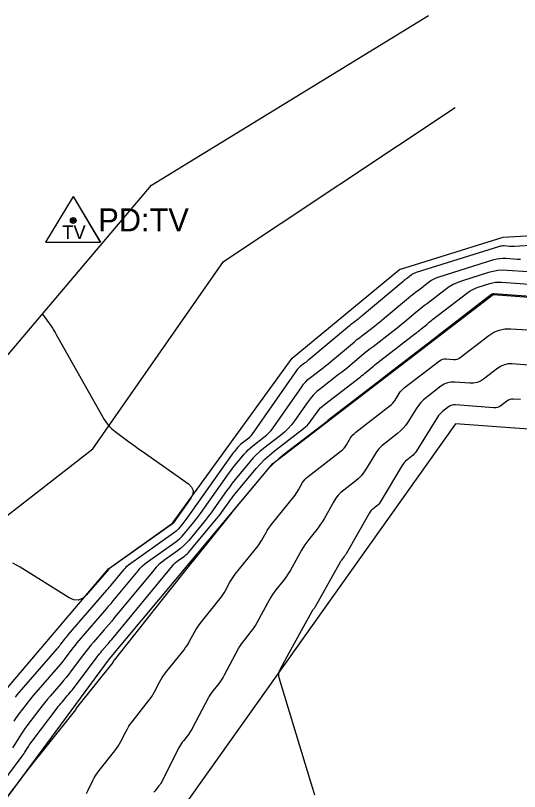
# Model space of a CAD drawing. Extents: x 1574966 to 1597594, y 720505 to 737840.
# Drawn here: x 1577580.8 to 1577690.4, y 724330.5 to 724499.2 of the extents above; entities that cross this region are included whole.
import ezdxf

# ---------------------------------------------------------------- set-up
doc = ezdxf.new("R2010")
doc.units = 0
for name, color, linetype in [('Default', 7, 'Continuous'), ('R_Contours', 7, 'Continuous'), ('S_BREAKLINE', 7, 'Continuous'), ('S_SECONDARY_CTL', 7, 'Continuous'), ('S_SECONDARY_CTL_ANNOT', 7, 'Continuous'), ('S_STREAM', 7, 'Continuous')]:
    doc.layers.add(name, color=color, linetype=linetype)

msp = doc.modelspace()

# ---------------------------------------------------------------- linework, layer by layer
at = {"layer": 'Default'}
for points in [[(1577593.33, 724454.59), (1577593.33, 724454.64), (1577593.33, 724454.59), (1577593.28, 724454.59), (1577593.33, 724454.59), (1577593.33, 724454.54), (1577593.33, 724454.59), (1577593.38, 724454.59)], [(1577593.33, 724454.59), (1577593.33, 724454.64), (1577593.33, 724454.59), (1577593.28, 724454.59), (1577593.33, 724454.59), (1577593.33, 724454.54), (1577593.33, 724454.59), (1577593.38, 724454.59)], [(1577593.33, 724454.59), (1577593.33, 724454.64), (1577593.33, 724454.59), (1577593.28, 724454.59), (1577593.33, 724454.59), (1577593.33, 724454.54), (1577593.33, 724454.59), (1577593.38, 724454.59)], [(1577593.33, 724454.58), (1577593.33, 724454.63), (1577593.33, 724454.58), (1577593.28, 724454.58), (1577593.33, 724454.58), (1577593.33, 724454.53), (1577593.33, 724454.58), (1577593.38, 724454.58)], [(1577593.33, 724454.58), (1577593.33, 724454.63), (1577593.33, 724454.58), (1577593.28, 724454.58), (1577593.33, 724454.58), (1577593.33, 724454.53), (1577593.33, 724454.58), (1577593.38, 724454.58)], [(1577593.33, 724454.58), (1577593.33, 724454.63), (1577593.33, 724454.58), (1577593.28, 724454.58), (1577593.33, 724454.58), (1577593.33, 724454.53), (1577593.33, 724454.58), (1577593.38, 724454.58)], [(1577593.36, 724454.57), (1577593.36, 724454.62), (1577593.36, 724454.57), (1577593.31, 724454.57), (1577593.36, 724454.57), (1577593.36, 724454.52), (1577593.36, 724454.57), (1577593.41, 724454.57)], [(1577593.36, 724454.57), (1577593.36, 724454.62), (1577593.36, 724454.57), (1577593.31, 724454.57), (1577593.36, 724454.57), (1577593.36, 724454.52), (1577593.36, 724454.57), (1577593.41, 724454.57)], [(1577593.36, 724454.57), (1577593.36, 724454.62), (1577593.36, 724454.57), (1577593.31, 724454.57), (1577593.36, 724454.57), (1577593.36, 724454.52), (1577593.36, 724454.57), (1577593.41, 724454.57)], [(1577593.36, 724454.56), (1577593.36, 724454.61), (1577593.36, 724454.56), (1577593.31, 724454.56), (1577593.36, 724454.56), (1577593.36, 724454.51), (1577593.36, 724454.56), (1577593.41, 724454.56)], [(1577593.36, 724454.56), (1577593.36, 724454.61), (1577593.36, 724454.56), (1577593.31, 724454.56), (1577593.36, 724454.56), (1577593.36, 724454.51), (1577593.36, 724454.56), (1577593.41, 724454.56)], [(1577593.36, 724454.56), (1577593.36, 724454.61), (1577593.36, 724454.56), (1577593.31, 724454.56), (1577593.36, 724454.56), (1577593.36, 724454.51), (1577593.36, 724454.56), (1577593.41, 724454.56)]]:
    msp.add_lwpolyline(points, dxfattribs=at)
at = {"layer": 'R_Contours'}
for points in [[(1577699.92, 724449.62), (1577689.3, 724449), (1577689.03, 724448.99), (1577688.76, 724448.99), (1577688.48, 724448.99), (1577688.21, 724449.01), (1577687.11, 724449.09), (1577686.84, 724449.09), (1577686.57, 724449.08), (1577686.31, 724449.03), (1577686.04, 724448.96), (1577667.93, 724443.31), (1577667.66, 724443.21), (1577667.41, 724443.09), (1577667.16, 724442.95), (1577666.93, 724442.79), (1577666.03, 724442.09), (1577665.8, 724441.92), (1577665.58, 724441.74), (1577665.36, 724441.56), (1577665.14, 724441.38), (1577656.22, 724433.93), (1577656, 724433.74), (1577655.77, 724433.56), (1577655.54, 724433.38), (1577655.31, 724433.2), (1577654.38, 724432.48), (1577654.14, 724432.3), (1577653.91, 724432.12), (1577653.68, 724431.93), (1577653.46, 724431.75), (1577644.63, 724424.37), (1577644.39, 724424.17), (1577644.16, 724423.98), (1577643.92, 724423.8), (1577643.68, 724423.61), (1577642.72, 724422.87), (1577642.49, 724422.68), (1577642.27, 724422.47), (1577642.07, 724422.25), (1577641.89, 724422.01), (1577632.2, 724408.12), (1577631.99, 724407.84), (1577631.76, 724407.58), (1577631.52, 724407.34), (1577631.25, 724407.12), (1577630.1, 724406.24), (1577629.85, 724406.03), (1577629.61, 724405.82), (1577629.39, 724405.59), (1577629.18, 724405.35), (1577628.36, 724404.36), (1577628.15, 724404.11), (1577627.96, 724403.86), (1577627.76, 724403.6), (1577627.57, 724403.34), (1577618.06, 724389.91), (1577617.84, 724389.61), (1577617.63, 724389.32), (1577617.4, 724389.04), (1577617.17, 724388.76), (1577616.25, 724387.64), (1577616.01, 724387.37), (1577615.75, 724387.12), (1577615.48, 724386.88), (1577615.2, 724386.66), (1577605.37, 724379.7), (1577605.09, 724379.48), (1577604.82, 724379.25), (1577604.56, 724379), (1577604.33, 724378.73), (1577601.57, 724375.39), (1577601.34, 724375.11), (1577601.1, 724374.83), (1577600.87, 724374.56), (1577600.63, 724374.28), (1577592.23, 724364.58), (1577592.02, 724364.34), (1577591.81, 724364.09), (1577591.61, 724363.83), (1577591.41, 724363.57), (1577590.63, 724362.53), (1577590.43, 724362.28), (1577590.23, 724362.02), (1577590.02, 724361.77), (1577589.81, 724361.52), (1577581.14, 724351.53), (1577580.94, 724351.3), (1577580.75, 724351.06)], [(1577580.52, 724345.83), (1577580.88, 724346.36), (1577581.25, 724346.89), (1577581.63, 724347.4), (1577583.18, 724349.46), (1577583.57, 724349.97), (1577583.97, 724350.47), (1577584.38, 724350.97), (1577584.8, 724351.46), (1577590.18, 724357.66), (1577590.61, 724358.16), (1577591.03, 724358.67), (1577591.44, 724359.19), (1577591.84, 724359.71), (1577593.43, 724361.82), (1577593.83, 724362.35), (1577594.24, 724362.86), (1577594.66, 724363.37), (1577595.09, 724363.88), (1577600.22, 724369.79), (1577600.68, 724370.33), (1577601.14, 724370.88), (1577601.6, 724371.42), (1577602.06, 724371.97), (1577607.47, 724378.52), (1577607.93, 724379.05), (1577608.43, 724379.54), (1577608.96, 724380), (1577609.52, 724380.42), (1577615.45, 724384.63), (1577616.01, 724385.06), (1577616.54, 724385.51), (1577617.03, 724386.01), (1577617.5, 724386.53), (1577619.3, 724388.7), (1577619.74, 724389.25), (1577620.18, 724389.8), (1577620.6, 724390.37), (1577621.01, 724390.94), (1577627.15, 724399.6), (1577627.54, 724400.14), (1577627.95, 724400.68), (1577628.36, 724401.21), (1577628.79, 724401.73), (1577630.51, 724403.81), (1577630.95, 724404.31), (1577631.42, 724404.79), (1577631.91, 724405.24), (1577632.43, 724405.67), (1577634.84, 724407.51), (1577635.4, 724407.98), (1577635.92, 724408.48), (1577636.4, 724409.02), (1577636.84, 724409.6), (1577643.05, 724418.51), (1577643.47, 724419.07), (1577643.93, 724419.58), (1577644.42, 724420.06), (1577644.95, 724420.5), (1577647.16, 724422.2), (1577647.71, 724422.62), (1577648.25, 724423.05), (1577648.79, 724423.49), (1577649.33, 724423.93), (1577654.54, 724428.29), (1577655.07, 724428.73), (1577655.61, 724429.16), (1577656.15, 724429.59), (1577656.69, 724430.01), (1577658.87, 724431.69), (1577659.41, 724432.11), (1577659.95, 724432.53), (1577660.49, 724432.97), (1577661.02, 724433.41), (1577666.3, 724437.82), (1577666.82, 724438.25), (1577667.35, 724438.68), (1577667.88, 724439.1), (1577668.42, 724439.52), (1577670.58, 724441.18), (1577671.13, 724441.57), (1577671.71, 724441.9), (1577672.32, 724442.19), (1577672.96, 724442.41), (1577684.87, 724446.14), (1577685.5, 724446.3), (1577686.13, 724446.4), (1577686.76, 724446.45), (1577687.41, 724446.43), (1577690, 724446.24), (1577690.65, 724446.21)], [(1577692.28, 724443.44), (1577687.7, 724443.77), (1577686.68, 724443.8), (1577685.68, 724443.73), (1577684.69, 724443.57), (1577683.7, 724443.31), (1577677.99, 724441.52), (1577676.98, 724441.16), (1577676.02, 724440.72), (1577675.1, 724440.19), (1577674.23, 724439.57), (1577670.39, 724436.62), (1577669.75, 724436.13), (1577669.12, 724435.62), (1577668.49, 724435.12), (1577667.87, 724434.6), (1577665.39, 724432.53), (1577664.77, 724432.01), (1577664.14, 724431.51), (1577663.51, 724431), (1577662.87, 724430.51), (1577658.56, 724427.2), (1577657.93, 724426.71), (1577657.3, 724426.21), (1577656.67, 724425.7), (1577656.06, 724425.19), (1577653.59, 724423.13), (1577652.98, 724422.62), (1577652.35, 724422.12), (1577651.72, 724421.62), (1577651.09, 724421.13), (1577647.19, 724418.13), (1577646.35, 724417.44), (1577645.58, 724416.69), (1577644.87, 724415.88), (1577644.22, 724415.02), (1577641.47, 724411.08), (1577640.8, 724410.2), (1577640.07, 724409.38), (1577639.28, 724408.61), (1577638.43, 724407.91), (1577634.77, 724405.09), (1577633.97, 724404.45), (1577633.22, 724403.76), (1577632.51, 724403.04), (1577631.83, 724402.27), (1577629.22, 724399.11), (1577628.57, 724398.31), (1577627.94, 724397.51), (1577627.33, 724396.69), (1577626.73, 724395.86), (1577623.97, 724391.97), (1577623.36, 724391.12), (1577622.73, 724390.28), (1577622.08, 724389.46), (1577621.42, 724388.64), (1577618.48, 724385.1), (1577617.92, 724384.47), (1577617.33, 724383.89), (1577616.71, 724383.34), (1577616.04, 724382.84), (1577613.31, 724380.9), (1577612.65, 724380.4), (1577612.02, 724379.86), (1577611.44, 724379.27), (1577610.88, 724378.65), (1577602.29, 724368.25), (1577601.74, 724367.58), (1577601.18, 724366.92), (1577600.62, 724366.26), (1577600.05, 724365.6), (1577597.78, 724362.98), (1577597.22, 724362.32), (1577596.67, 724361.65), (1577596.13, 724360.97), (1577595.6, 724360.28), (1577592.92, 724356.73), (1577592.38, 724356.02), (1577591.82, 724355.32), (1577591.26, 724354.63), (1577590.68, 724353.95), (1577588.33, 724351.25), (1577587.75, 724350.57), (1577587.19, 724349.88), (1577586.63, 724349.18), (1577586.09, 724348.47), (1577583.3, 724344.78), (1577582.87, 724344.2), (1577582.46, 724343.61), (1577582.06, 724343.02), (1577581.67, 724342.42), (1577580.14, 724339.99)], [(1577576.62, 724330.68), (1577582.06, 724337.91), (1577582.28, 724338.19), (1577582.48, 724338.48), (1577582.68, 724338.78), (1577582.87, 724339.08), (1577583.63, 724340.28), (1577583.82, 724340.58), (1577584.02, 724340.88), (1577584.23, 724341.17), (1577584.44, 724341.45), (1577589.85, 724348.62), (1577590.11, 724348.97), (1577590.38, 724349.31), (1577590.66, 724349.64), (1577590.94, 724349.97), (1577592.08, 724351.29), (1577592.37, 724351.62), (1577592.64, 724351.96), (1577592.91, 724352.3), (1577593.18, 724352.64), (1577598.56, 724359.79), (1577598.82, 724360.12), (1577599.07, 724360.44), (1577599.34, 724360.76), (1577599.6, 724361.08), (1577600.69, 724362.33), (1577600.96, 724362.64), (1577601.23, 724362.96), (1577601.49, 724363.27), (1577601.76, 724363.59), (1577615.01, 724379.63), (1577615.28, 724379.94), (1577615.57, 724380.22), (1577615.88, 724380.49), (1577616.2, 724380.74), (1577617.55, 724381.69), (1577617.87, 724381.94), (1577618.18, 724382.21), (1577618.47, 724382.5), (1577618.75, 724382.8), (1577624.61, 724389.87), (1577624.96, 724390.3), (1577625.3, 724390.74), (1577625.64, 724391.19), (1577625.96, 724391.64), (1577627.25, 724393.46), (1577627.58, 724393.91), (1577627.91, 724394.35), (1577628.25, 724394.79), (1577628.61, 724395.22), (1577633.16, 724400.73), (1577634.07, 724401.76), (1577635.03, 724402.74), (1577636.04, 724403.66), (1577637.1, 724404.52), (1577643.47, 724409.4), (1577643.91, 724409.78), (1577644.33, 724410.18), (1577644.71, 724410.61), (1577645.06, 724411.08), (1577646.4, 724413), (1577646.75, 724413.46), (1577647.14, 724413.89), (1577647.55, 724414.3), (1577648, 724414.67), (1577655.81, 724420.67), (1577656.14, 724420.92), (1577656.46, 724421.18), (1577656.78, 724421.43), (1577657.09, 724421.69), (1577658.35, 724422.74), (1577658.66, 724423), (1577658.98, 724423.26), (1577659.3, 724423.52), (1577659.63, 724423.77), (1577667.68, 724429.96), (1577668.01, 724430.21), (1577668.33, 724430.47), (1577668.65, 724430.73), (1577668.97, 724430.99), (1577670.24, 724432.05), (1577670.56, 724432.32), (1577670.88, 724432.58), (1577671.21, 724432.83), (1577671.53, 724433.09), (1577679.18, 724438.96), (1577679.71, 724439.33), (1577680.27, 724439.65), (1577680.85, 724439.93), (1577681.46, 724440.15), (1577683.96, 724440.92), (1577684.58, 724441.09), (1577685.22, 724441.19), (1577685.86, 724441.24), (1577686.51, 724441.22), (1577695.56, 724440.57)], [(1577698.85, 724437.7), (1577684.82, 724438.71), (1577684.78, 724438.71), (1577684.75, 724438.7), (1577684.72, 724438.7), (1577684.68, 724438.69), (1577684.55, 724438.65), (1577684.52, 724438.64), (1577684.49, 724438.62), (1577684.46, 724438.61), (1577684.43, 724438.59), (1577672.67, 724429.55), (1577672.66, 724429.54), (1577672.64, 724429.53), (1577672.63, 724429.52), (1577672.61, 724429.5), (1577672.56, 724429.45), (1577672.54, 724429.44), (1577672.53, 724429.43), (1577672.51, 724429.42), (1577672.5, 724429.41), (1577660.69, 724420.34), (1577660.68, 724420.33), (1577660.67, 724420.32), (1577660.65, 724420.31), (1577660.64, 724420.3), (1577660.59, 724420.25), (1577660.58, 724420.24), (1577660.56, 724420.23), (1577660.55, 724420.22), (1577660.54, 724420.21), (1577648.72, 724411.13), (1577648.7, 724411.12), (1577648.69, 724411.1), (1577648.67, 724411.09), (1577648.66, 724411.07), (1577648.62, 724411.01), (1577648.6, 724410.99), (1577648.59, 724410.98), (1577648.58, 724410.96), (1577648.56, 724410.95), (1577639.4, 724403.92), (1577638.08, 724402.85), (1577636.83, 724401.71), (1577635.64, 724400.5), (1577634.52, 724399.22), (1577628.02, 724391.37), (1577628, 724391.35), (1577627.99, 724391.33), (1577627.98, 724391.32), (1577627.96, 724391.3), (1577627.88, 724391.2), (1577627.88, 724391.2), (1577619.28, 724380.5), (1577619.28, 724380.49), (1577619.27, 724380.47), (1577619.26, 724380.46), (1577619.25, 724380.45), (1577619.22, 724380.4), (1577619.22, 724380.38), (1577619.21, 724380.37), (1577619.2, 724380.36), (1577619.19, 724380.35), (1577610.74, 724369.8), (1577610.72, 724369.77), (1577610.7, 724369.75), (1577610.69, 724369.72), (1577610.67, 724369.69), (1577610.61, 724369.58), (1577610.6, 724369.56), (1577610.58, 724369.53), (1577610.56, 724369.51), (1577610.55, 724369.48), (1577602.25, 724359.1), (1577602.23, 724359.06), (1577602.2, 724359.02), (1577602.17, 724358.98), (1577602.15, 724358.93), (1577602.06, 724358.76), (1577602.04, 724358.72), (1577602.01, 724358.68), (1577601.98, 724358.64), (1577601.96, 724358.6), (1577594.04, 724348.61), (1577594.02, 724348.59), (1577594, 724348.56), (1577593.99, 724348.54), (1577593.97, 724348.51), (1577593.92, 724348.4), (1577593.91, 724348.38), (1577593.89, 724348.35), (1577593.87, 724348.33), (1577593.86, 724348.3), (1577585.75, 724338.14), (1577585.75, 724338.13), (1577585.74, 724338.12), (1577585.74, 724338.11), (1577585.73, 724338.11), (1577585.72, 724338.08), (1577585.71, 724338.07), (1577585.71, 724338.06), (1577585.7, 724338.05), (1577585.7, 724338.05), (1577583.44, 724335.23), (1577583.06, 724334.75), (1577582.69, 724334.28), (1577582.32, 724333.8), (1577581.95, 724333.32), (1577577.69, 724327.67)], [(1577586.68, 724434.3), (1577588.54, 724431.64), (1577588.84, 724431.2), (1577589.14, 724430.75), (1577589.42, 724430.29), (1577589.69, 724429.82), (1577600.11, 724411.39), (1577600.6, 724410.64), (1577601.15, 724409.95), (1577601.77, 724409.32), (1577602.47, 724408.75), (1577605.39, 724406.62), (1577606.12, 724406.09), (1577606.86, 724405.56), (1577607.59, 724405.03), (1577608.33, 724404.51), (1577618.4, 724397.38), (1577619.11, 724396.7), (1577619.44, 724395.96), (1577619.38, 724395.15), (1577618.93, 724394.28), (1577615.1, 724388.88), (1577615.09, 724388.86), (1577615.08, 724388.84), (1577615.06, 724388.83), (1577615.05, 724388.81), (1577615, 724388.75), (1577614.99, 724388.74), (1577614.97, 724388.72), (1577614.96, 724388.71), (1577614.94, 724388.7), (1577601.22, 724378.97), (1577601.21, 724378.96), (1577601.2, 724378.95), (1577601.19, 724378.94), (1577601.19, 724378.93), (1577601.08, 724378.81), (1577601.08, 724378.8), (1577601.07, 724378.79), (1577601.06, 724378.78), (1577601.05, 724378.77), (1577596.21, 724373.18), (1577595.37, 724372.45), (1577594.47, 724372.11), (1577593.51, 724372.17), (1577592.49, 724372.62), (1577581.81, 724379.31), (1577580.23, 724380.12)], [(1577596.23, 724330.08), (1577596.52, 724330.65), (1577597.65, 724332.95), (1577597.94, 724333.51), (1577598.27, 724334.06), (1577598.62, 724334.59), (1577599, 724335.1), (1577602.41, 724339.37), (1577602.78, 724339.86), (1577603.13, 724340.37), (1577603.45, 724340.89), (1577603.74, 724341.43), (1577604.85, 724343.63), (1577605.14, 724344.17), (1577605.46, 724344.7), (1577605.8, 724345.21), (1577606.17, 724345.7), (1577609.74, 724350.2), (1577610.09, 724350.67), (1577610.43, 724351.16), (1577610.74, 724351.67), (1577611.03, 724352.19), (1577612.12, 724354.3), (1577612.41, 724354.82), (1577612.72, 724355.32), (1577613.06, 724355.81), (1577613.42, 724356.29), (1577617.46, 724361.35), (1577617.8, 724361.79), (1577618.11, 724362.25), (1577618.41, 724362.72), (1577618.68, 724363.2), (1577619.73, 724365.16), (1577620, 724365.65), (1577620.29, 724366.12), (1577620.61, 724366.57), (1577620.95, 724367.01), (1577625.31, 724372.46), (1577625.63, 724372.87), (1577625.92, 724373.3), (1577626.2, 724373.74), (1577626.46, 724374.19), (1577627.46, 724376.01), (1577627.72, 724376.46), (1577628, 724376.9), (1577628.3, 724377.32), (1577628.61, 724377.74), (1577633.27, 724383.54), (1577633.57, 724383.92), (1577633.85, 724384.32), (1577634.11, 724384.73), (1577634.36, 724385.15), (1577635.31, 724386.85), (1577635.56, 724387.27), (1577635.82, 724387.68), (1577636.1, 724388.07), (1577636.4, 724388.46), (1577641.33, 724394.58), (1577641.61, 724394.94), (1577641.88, 724395.32), (1577642.12, 724395.7), (1577642.36, 724396.09), (1577643.26, 724397.67), (1577643.51, 724398.05), (1577643.78, 724398.41), (1577644.09, 724398.73), (1577644.44, 724399.02), (1577651.66, 724404.59), (1577651.99, 724404.87), (1577652.29, 724405.18), (1577652.56, 724405.51), (1577652.8, 724405.87), (1577653.69, 724407.37), (1577653.93, 724407.73), (1577654.2, 724408.06), (1577654.5, 724408.37), (1577654.83, 724408.65), (1577662.29, 724414.39), (1577662.6, 724414.66), (1577662.89, 724414.95), (1577663.15, 724415.26), (1577663.39, 724415.61), (1577664.27, 724417.02), (1577664.5, 724417.36), (1577664.77, 724417.68), (1577665.05, 724417.97), (1577665.37, 724418.24), (1577673.03, 724424.13), (1577673.36, 724424.34), (1577673.71, 724424.48), (1577674.09, 724424.55), (1577674.48, 724424.56), (1577676.1, 724424.43), (1577676.49, 724424.44), (1577676.86, 724424.51), (1577677.21, 724424.65), (1577677.55, 724424.87), (1577683.73, 724429.63), (1577684.83, 724430.34), (1577686.01, 724430.82), (1577687.25, 724431.08), (1577688.56, 724431.1), (1577695.86, 724430.62)], [(1577692.39, 724423.22), (1577688.82, 724423.45), (1577687.97, 724423.44), (1577687.17, 724423.27), (1577686.41, 724422.96), (1577685.69, 724422.5), (1577682.61, 724420.12), (1577681.93, 724419.69), (1577681.21, 724419.39), (1577680.44, 724419.24), (1577679.63, 724419.24), (1577676.32, 724419.49), (1577675.51, 724419.48), (1577674.75, 724419.33), (1577674.02, 724419.04), (1577673.34, 724418.61), (1577670.21, 724416.19), (1577669.56, 724415.65), (1577668.97, 724415.05), (1577668.44, 724414.41), (1577667.96, 724413.71), (1577666.16, 724410.82), (1577665.68, 724410.12), (1577665.15, 724409.47), (1577664.56, 724408.88), (1577663.91, 724408.33), (1577661.12, 724406.19), (1577660.46, 724405.63), (1577659.86, 724405.02), (1577659.32, 724404.35), (1577658.85, 724403.63), (1577656.94, 724400.44), (1577656.49, 724399.76), (1577655.98, 724399.13), (1577655.42, 724398.55), (1577654.8, 724398.03), (1577652.19, 724396.02), (1577651.57, 724395.49), (1577651.01, 724394.91), (1577650.51, 724394.27), (1577650.07, 724393.59), (1577647.91, 724389.8), (1577647.55, 724389.2), (1577647.17, 724388.61), (1577646.77, 724388.04), (1577646.34, 724387.48), (1577644.57, 724385.29), (1577644.14, 724384.74), (1577643.74, 724384.17), (1577643.36, 724383.58), (1577643.01, 724382.97), (1577640.52, 724378.52), (1577640.19, 724377.97), (1577639.84, 724377.43), (1577639.47, 724376.9), (1577639.08, 724376.39), (1577637.46, 724374.38), (1577637.07, 724373.87), (1577636.7, 724373.34), (1577636.36, 724372.8), (1577636.04, 724372.24), (1577633.27, 724367.2), (1577632.98, 724366.69), (1577632.67, 724366.2), (1577632.34, 724365.73), (1577631.99, 724365.27), (1577630.53, 724363.45), (1577630.18, 724362.99), (1577629.85, 724362.51), (1577629.54, 724362.02), (1577629.25, 724361.51), (1577626.21, 724355.82), (1577625.96, 724355.37), (1577625.68, 724354.93), (1577625.39, 724354.51), (1577625.08, 724354.1), (1577623.8, 724352.49), (1577623.49, 724352.09), (1577623.2, 724351.66), (1577622.93, 724351.23), (1577622.68, 724350.78), (1577619.33, 724344.34), (1577619.13, 724343.97), (1577618.9, 724343.61), (1577618.66, 724343.25), (1577618.4, 724342.91), (1577617.34, 724341.57), (1577617.08, 724341.23), (1577616.84, 724340.88), (1577616.62, 724340.51), (1577616.42, 724340.13), (1577612.79, 724332.96), (1577612.62, 724332.65), (1577612.44, 724332.34), (1577612.24, 724332.04), (1577612.02, 724331.76), (1577611.12, 724330.63), (1577610.91, 724330.35)], [(1577690.64, 724415.7), (1577689.07, 724415.8), (1577688.69, 724415.8), (1577688.33, 724415.72), (1577687.99, 724415.58), (1577687.66, 724415.38), (1577686.33, 724414.35), (1577685.99, 724414.13), (1577685.64, 724413.99), (1577685.26, 724413.91), (1577684.86, 724413.91), (1577676.48, 724414.55), (1577676.08, 724414.55), (1577675.69, 724414.47), (1577675.33, 724414.33), (1577674.99, 724414.11), (1577673.67, 724413.09), (1577673.35, 724412.82), (1577673.06, 724412.53), (1577672.8, 724412.22), (1577672.57, 724411.88), (1577667.94, 724404.44), (1577667.74, 724404.16), (1577667.52, 724403.89), (1577667.28, 724403.64), (1577667.01, 724403.42), (1577665.9, 724402.56), (1577665.63, 724402.33), (1577665.39, 724402.09), (1577665.17, 724401.82), (1577664.98, 724401.53), (1577660.13, 724393.42), (1577659.98, 724393.18), (1577659.8, 724392.97), (1577659.61, 724392.77), (1577659.4, 724392.59), (1577658.51, 724391.91), (1577658.3, 724391.73), (1577658.11, 724391.53), (1577657.94, 724391.31), (1577657.79, 724391.07), (1577652.71, 724382.18), (1577652.62, 724382.02), (1577652.52, 724381.87), (1577652.41, 724381.72), (1577652.3, 724381.57), (1577651.83, 724380.99), (1577651.72, 724380.84), (1577651.61, 724380.69), (1577651.51, 724380.54), (1577651.42, 724380.38), (1577646, 724370.69), (1577645.94, 724370.59), (1577645.88, 724370.5), (1577645.82, 724370.42), (1577645.76, 724370.33), (1577645.49, 724369.99), (1577645.42, 724369.91), (1577645.36, 724369.82), (1577645.3, 724369.73), (1577645.25, 724369.64), (1577639.49, 724359.12), (1577639.48, 724359.1), (1577639.47, 724359.08), (1577639.45, 724359.06), (1577639.44, 724359.04), (1577639.38, 724358.97), (1577639.37, 724358.95), (1577639.35, 724358.93), (1577639.34, 724358.91), (1577639.33, 724358.89), (1577638.21, 724356.8), (1577638.06, 724356.44), (1577637.98, 724356.07), (1577637.99, 724355.7), (1577638.06, 724355.32), (1577644.94, 724332.64), (1577645.38, 724331.23), (1577645.83, 724329.81)]]:
    msp.add_lwpolyline(points, dxfattribs=at)
at = {"layer": 'S_BREAKLINE'}
for p, q in [((1577610.41, 724462.27), (1577670.66, 724499.17)), ((1577626.02, 724445.68), (1577676.42, 724479.15)), ((1577576, 724421.71), (1577610.41, 724462.27)), ((1577597.66, 724405.03), (1577626.02, 724445.68)), ((1577676.48, 724410.43), (1577558.94, 724245.17)), ((1577881.29, 724395.93), (1577676.48, 724410.43)), ((1577551.69, 724369.48), (1577597.66, 724405.03))]:
    msp.add_line(p, q, dxfattribs=at)
at = {"layer": 'S_SECONDARY_CTL'}
for p, q in [((1577593.37, 724459.84), (1577587.35, 724449.93)), ((1577593.37, 724459.84), (1577587.35, 724449.93)), ((1577593.37, 724459.84), (1577587.35, 724449.93)), ((1577593.37, 724459.82), (1577587.35, 724449.91)), ((1577593.37, 724459.82), (1577587.35, 724449.91)), ((1577593.37, 724459.82), (1577587.35, 724449.91)), ((1577593.37, 724459.84), (1577599.26, 724449.93)), ((1577593.37, 724459.84), (1577599.26, 724449.93)), ((1577593.37, 724459.84), (1577599.26, 724449.93)), ((1577593.37, 724459.82), (1577599.27, 724449.91)), ((1577593.37, 724459.82), (1577599.27, 724449.91)), ((1577593.37, 724459.82), (1577599.27, 724449.91)), ((1577587.35, 724449.93), (1577599.26, 724449.93)), ((1577587.35, 724449.93), (1577599.26, 724449.93)), ((1577587.35, 724449.93), (1577599.26, 724449.93)), ((1577587.35, 724449.91), (1577599.27, 724449.91)), ((1577587.35, 724449.91), (1577599.27, 724449.91)), ((1577587.35, 724449.91), (1577599.27, 724449.91))]:
    msp.add_line(p, q, dxfattribs=at)
for centre, radius in [((1577593.37, 724454.62), 0.622), ((1577593.37, 724454.62), 0.622), ((1577593.37, 724454.62), 0.622), ((1577593.37, 724454.6), 0.622), ((1577593.37, 724454.6), 0.622), ((1577593.37, 724454.6), 0.622), ((1577593.37, 724454.62), 0.365), ((1577593.37, 724454.62), 0.365), ((1577593.37, 724454.62), 0.365), ((1577593.37, 724454.6), 0.365), ((1577593.37, 724454.6), 0.365), ((1577593.37, 724454.6), 0.365), ((1577593.37, 724454.62), 0.207), ((1577593.37, 724454.62), 0.207), ((1577593.37, 724454.62), 0.207), ((1577593.37, 724454.6), 0.207), ((1577593.37, 724454.6), 0.207), ((1577593.37, 724454.6), 0.207)]:
    msp.add_circle(centre, radius, dxfattribs=at)
at = {"layer": 'S_STREAM'}
for p, q in [((1577664.3, 724443.95), (1577686.9, 724451.03)), ((1577686.9, 724451.03), (1577701.32, 724451.87)), ((1577640.99, 724424.7), (1577664.3, 724443.95)), ((1577636.75, 724401.82), (1577684.72, 724438.57)), ((1577684.72, 724438.57), (1577799.62, 724429.96)), ((1577614.93, 724388.82), (1577640.99, 724424.7)), ((1577601.27, 724359.34), (1577636.75, 724401.82)), ((1577601.06, 724378.94), (1577614.93, 724388.82)), ((1577577.85, 724351.6), (1577601.06, 724378.94)), ((1577569.87, 724317.01), (1577601.27, 724359.34))]:
    msp.add_line(p, q, dxfattribs=at)

# ---------------------------------------------------------------- texts
at = {"layer": 'S_SECONDARY_CTL'}
for p in [(1577590.96, 724450.6), (1577590.96, 724450.6), (1577590.96, 724450.6), (1577590.96, 724450.58), (1577590.96, 724450.58), (1577590.96, 724450.58)]:
    msp.add_text('TV', height=3, rotation=360, dxfattribs=at).set_placement(p)
at = {"layer": 'S_SECONDARY_CTL_ANNOT'}
msp.add_text('PD:TV', height=5, dxfattribs=at).set_placement((1577598.82, 724452.26))

doc.saveas('drawing.dxf')
